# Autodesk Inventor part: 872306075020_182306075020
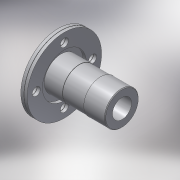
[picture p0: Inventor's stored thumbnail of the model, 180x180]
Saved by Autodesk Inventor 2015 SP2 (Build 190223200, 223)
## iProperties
Created: 2017-02
Part Number: 872306075020_182306075020
Material: PVC-Piping
Description: PLASSON FLANGE ADAPTOR WITH METAL FLANGE 75-2"
Document SubType Name: Modeling
Designer: KIM
Mass: 92.6774 g
Surface Area: 199.44 cm^2
Volume: 66.1981 cm^3
Density: 1.4 g/cm^3
Appearance: Smooth - White
Author: Кирилл
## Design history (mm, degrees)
derived "872306.ipt"
feature "Solid1::872306.ipt"
tag "TaggingFeature1"
body "Solid1"
other parameters: "d73" = 14.2, "d74" = 90 deg, "d75" = 0.3, "d76" = 165, "d77" = 18, "d78" = 62.5, "d80" = 0, "d82" = 360 deg, "d96" = 0.3, "d99" = 360 deg, "d101" = 75, "d103" = 142, "d104" = 1.5, "d107" = 97.5, "d108" = 3.55, "d116" = 73.5, "d117" = 47.33333, "d118" = 47.33333, "d119" = 75, "d120" = 3.75, "d_" = 75, "H_" = 142, "D_" = 165, "Dp_" = 125, "S_" = 18
